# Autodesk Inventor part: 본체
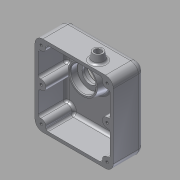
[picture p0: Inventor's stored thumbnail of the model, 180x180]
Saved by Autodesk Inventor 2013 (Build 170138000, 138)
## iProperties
Created: 2015-10
Part Number: 본체
Material: 알루미늄 6061
Document SubType Name: Modeling
Designer: mduedu
Density: 1 g/cm^3
Author: mduedu
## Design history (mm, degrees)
sketch "스케치1"
  geometry: L1 (-50, -51.5)-(50, -51.5); L2 (50, -51.5)-(50, 51.5); L3 (50, 51.5)-(-50, 51.5); L4 (-50, 51.5)-(-50, -51.5); L5 (-50, -51.5)-(50, 51.5); L6 (50, -51.5)-(-50, 51.5); 1 further point
  constraints: 12 end point, 2 midpoint, 2 parallel, 1 horizontal, 1 perpendicular
  dimensions: "d0" = 100 distance of L3.end L2.end; "d1" = 103 distance of L2.end L1.end
extrude "돌출1" new body sketch "스케치1" distance "d2" = 40; taper "d3" = 0 deg
fillet "모깎기1" dims "d4" = 10
fillet "모깎기2" dims "d5" = 8
feature "쉘1" dims "d6" = 4
sketch "스케치2"
  geometry: L1 (-50, 41.5)-(-50, -41.5) reference; L2 (50, -41.5)-(50, 41.5) reference; L3 (-50, 0)-(50, 0); L4 (40, 51.5)-(-40, 51.5) reference; L5 (-40, -51.5)-(40, -51.5) reference; L6 (0, 51.5)-(0, -51.5); C1 r 6 at (-42, 43.5); C2 r 6 at (-42, 0); C3 r 6 at (-42, -43.5); C4 r 6 at (42, 43.5); C5 r 6 at (42, 0); C6 r 6 at (42, -43.5); 1 further point
  constraints: 6 centre point, 4 end point, 4 midpoint, 4 symmetric about line, 1 point on line, 1 vertical alignment, 4 other
  dimensions: "d7" = 12 diameter of C1; "d10" = 12 diameter of C2 (= d7); "d16" = 8 distance from line of C1.centre L1; "d17" = 8 distance from line of C1.centre L4
extrude "돌출2" join sketch "스케치2" stored distance "d11" = 0; taper "d12" = 0 deg
fillet "모깎기3" dims "d13" = 3
sketch "스케치3"
  geometry: A1 r 6 centre (-42, 43.5) between (-42.667, 37.537) and (-36.037, 44.167) reference; A2 r 6 centre (42, 43.5) between (36.037, 44.167) and (42.667, 37.537) reference; A3 r 6 centre (42, 0) between (42.667, 5.963) and (42.667, -5.963) reference; A4 r 6 centre (-42, 0) between (-42.667, -5.963) and (-42.667, 5.963) reference; A5 r 6 centre (-42, -43.5) between (-36.037, -44.167) and (-42.667, -37.537) reference; A6 r 6 centre (42, -43.5) between (42.667, -37.537) and (36.037, -44.167) reference; 7 further points
  constraints: 6 coincident
hole "구멍1" sketch "스케치3" at (-42, 43.5), (-42, 0), (-42, -43.5), (42, -43.5), (42, 0), (42, 43.5) diameter "d18" = 3.242; stored, may be unused: countersink angle "d22" = 90 deg, drill point angle "d24" = 118 deg; dims "d19" = 12, "d20" = 4, "d21" = 2, "d23" = 14
sketch "스케치4"
  geometry: L1 (90, 0)-(80, 0) reference; L2 (90, 0)-(90, 32) reference; C1 r 8 at (58.594, 12); 1 further point
  constraints: 1 centre point
  dimensions: "d25" = 16 diameter of C1; "d26" = 12 distance from line of L1 C1.centre; "d27" = 31.406 distance from line of C1.centre L2
extrude "돌출3" join sketch "스케치4" distance "d28" = 10; taper "d29" = -10 deg
sketch "스케치5"
  geometry: C1 r 8 at (0, 0) reference; C2 r 4 at (0, 0); 1 further point
  constraints: 1 centre point, 1 coincident
  dimensions: "d30" = 8 diameter of C2
extrude "돌출4" cut sketch "스케치5" stored distance "d31" = 0; taper "d32" = 0 deg
chamfer "모따기1" distance "d33" = 0.5; stored, may be unused: second distance "d34" = 2, angle "d35" = 45 deg
fillet "모깎기4" dims "d36" = 3
sketch "스케치6"
  geometry: L1 (73, 8)-(-7, 8) reference; L2 (-17, -2)-(-17, -85) reference; C1 r 21.5 at (23, -32); 1 further point
  constraints: 1 centre point
  dimensions: "d37" = 43 diameter of C1; "d38" = 40 distance from line of C1.centre L1; "d39" = 40 distance from line of C1.centre L2
extrude "돌출5" join sketch "스케치6" distance "d40" = 15; taper "d41" = -10 deg
hole "구멍2" diameter "d44" = 25; stored, may be unused: countersink angle "d48" = 90 deg, drill point angle "d50" = 0 deg; dims "d42" = 10, "d43" = 10, "d45" = 10, "d46" = 4, "d47" = 2, "d49" = 7
hole "구멍3" diameter "d53" = 20; stored, may be unused: countersink angle "d57" = 90 deg, drill point angle "d59" = 0 deg; dims "d51" = 10, "d52" = 10, "d54" = 10, "d55" = 32, "d56" = 9, "d58" = 7
chamfer "모따기2" distance "d60" = 1; stored, may be unused: second distance "d61" = 2, angle "d62" = 45 deg
sketch "스케치7"
  geometry: L1 (-50, 41.5)-(-50, -41.5) reference; L2 (-40, -51.5)-(40, -51.5) reference; 2 further points
  constraints: 1 other
  dimensions: "d63" = 50 distance from line of point (0, -21.5) L1; "d64" = 30 distance from line of point (0, -21.5) L2
feature "엠보싱1" sketch "스케치7" dims "d0" = 100, "d1" = 103, "d65" = 0.5, "d66" = 0
fillet "모깎기5" dims "d67" = 3
fillet "모깎기6" dims "d68" = 0.3
chamfer "모따기3" distance "d69" = 0.5; stored, may be unused: second distance "d70" = 2, angle "d71" = 45 deg
node "솔리드1"
